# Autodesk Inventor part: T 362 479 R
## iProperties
Company: Mayer & Müller AG Schaltgeräte
Created: 2006-04
Part Number: T 362 479 R
Material: Durethan BKV30H
Document SubType Name: Modeling
Designer: I.Baliuc
Manufacturer: Standard
Standards Organization: Custom
Description: Sockel, rechts
Density: 0.94 g/cm^3
Zweck: für Abdeckung LBK
Author: T.Messerschmitt
Keywords: 362242
Revision Number: 362479 R
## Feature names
1. Extrusion2
2. Extrusion3
3. Rundung_0.5 [Fillet]
4. Extrusion4
5. Fase1 [Chamfer]
6. Fase2 [Chamfer]
7. Bohrung1 [Hole]
8. Extrusion5
9. Bohrung2 [Hole]
10. Extrusion6
